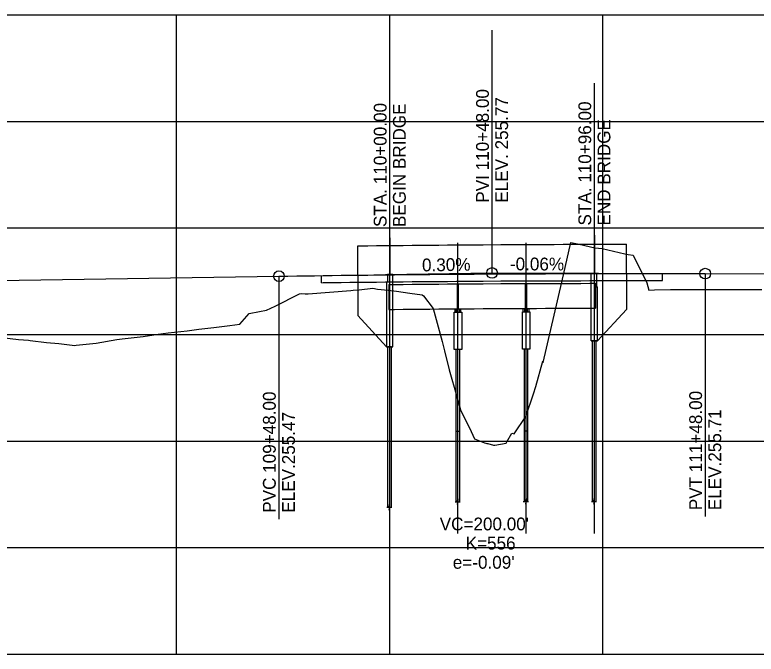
# Model space of a CAD drawing. Extents: x 1932071 to 1934815, y 598385 to 598883.
# Drawn here: x 1933216.8 to 1933564.6, y 598574.6 to 598874.6 of the extents above; entities that cross this region are included whole.
import ezdxf

# ---------------------------------------------------------------- set-up
doc = ezdxf.new("R2010")
doc.units = 0
for name, color, linetype in [('B_Centerline', 7, 'Continuous'), ('B_Concrete', 7, 'Continuous'), ('B_Pr_Abut_Wingwall', 7, 'Continuous'), ('B_Pr_Beam_Line', 7, 'Continuous'), ('B_Pr_Cap_Beams', 7, 'Continuous'), ('B_Pr_Columns', 7, 'Continuous'), ('B_Pr_Deck', 7, 'Continuous'), ('B_Pr_Rail', 7, 'Continuous'), ('BR_Pr_Cap_Beams', 7, 'Continuous'), ('Default', 7, 'Continuous'), ('R_Axis', 7, 'Continuous'), ('R_Exist Surface', 7, 'Continuous'), ('R_Grid', 7, 'Continuous'), ('R_Vert Alg', 7, 'Continuous'), ('R_Vert Alg Annot', 7, 'Continuous')]:
    doc.layers.add(name, color=color, linetype=linetype)

msp = doc.modelspace()

# ---------------------------------------------------------------- linework, layer by layer
at = {"layer": 'B_Centerline'}
for p, q in [((1933392.67, 598631.14), (1933392.67, 598767.58)), ((1933424.67, 598631.14), (1933424.67, 598767.58)), ((1933456.67, 598631.14), (1933456.67, 598767.58)), ((1933488.67, 598631.14), (1933488.67, 598767.58))]:
    msp.add_line(p, q, dxfattribs=at)
at = {"layer": 'B_Concrete'}
for p, q in [((1933377.67, 598752.42), (1933377.67, 598766.17)), ((1933503.67, 598753.17), (1933503.67, 598766.92)), ((1933360.67, 598748.87), (1933360.67, 598752.2)), ((1933520.67, 598749.83), (1933520.67, 598753.16))]:
    msp.add_line(p, q, dxfattribs=at)
for points in [[(1933377.67, 598766.17), (1933382.33, 598766.22), (1933386.5, 598766.27), (1933390.67, 598766.31), (1933394.83, 598766.35), (1933399, 598766.39), (1933403.17, 598766.43), (1933407.33, 598766.47), (1933411.5, 598766.51), (1933415.67, 598766.54), (1933419.83, 598766.58), (1933424, 598766.61), (1933428.17, 598766.64), (1933432.33, 598766.67), (1933436.5, 598766.7), (1933444.83, 598766.75), (1933449, 598766.77), (1933453.17, 598766.79), (1933457.33, 598766.81), (1933461.5, 598766.83), (1933465.67, 598766.84), (1933469.83, 598766.86), (1933474, 598766.87), (1933478.17, 598766.88), (1933482.33, 598766.89), (1933486.5, 598766.9), (1933490.67, 598766.91), (1933494.83, 598766.92), (1933499, 598766.92), (1933503.67, 598766.92)], [(1933360.67, 598748.87), (1933361.5, 598748.88), (1933365.67, 598748.94), (1933369.83, 598748.99), (1933374, 598749.04), (1933378.17, 598749.09), (1933382.33, 598749.14), (1933386.5, 598749.18), (1933390.67, 598749.23), (1933394.83, 598749.27), (1933399, 598749.31), (1933403.17, 598749.35), (1933407.33, 598749.39), (1933411.5, 598749.43), (1933415.67, 598749.46), (1933419.83, 598749.5), (1933424, 598749.53), (1933428.17, 598749.56), (1933432.33, 598749.59), (1933436.5, 598749.61), (1933444.83, 598749.66), (1933449, 598749.69), (1933453.17, 598749.71), (1933457.33, 598749.73), (1933461.5, 598749.75), (1933465.67, 598749.76), (1933469.83, 598749.78), (1933474, 598749.79), (1933478.17, 598749.8), (1933482.33, 598749.81), (1933486.5, 598749.82), (1933490.67, 598749.83), (1933494.83, 598749.83), (1933499, 598749.84), (1933503.17, 598749.84), (1933507.33, 598749.84), (1933511.5, 598749.84), (1933515.67, 598749.84), (1933519.83, 598749.83), (1933520.67, 598749.83)], [(1933392.17, 598747.99), (1933394.83, 598748.02), (1933399, 598748.06), (1933403.17, 598748.1), (1933407.33, 598748.14), (1933411.5, 598748.18), (1933415.67, 598748.21), (1933419.83, 598748.25), (1933424, 598748.28), (1933428.17, 598748.31), (1933432.33, 598748.34), (1933436.5, 598748.36), (1933444.83, 598748.41), (1933449, 598748.44), (1933453.17, 598748.46), (1933457.33, 598748.48), (1933461.5, 598748.5), (1933465.67, 598748.51), (1933469.83, 598748.53), (1933474, 598748.54), (1933478.17, 598748.55), (1933482.33, 598748.56), (1933486.5, 598748.57), (1933489.17, 598748.57)], [(1933392.17, 598736.33), (1933394.83, 598736.35), (1933399, 598736.4), (1933403.17, 598736.43), (1933407.33, 598736.47), (1933411.5, 598736.51), (1933415.67, 598736.55), (1933419.83, 598736.58), (1933424, 598736.61), (1933428.17, 598736.64), (1933432.33, 598736.67), (1933436.5, 598736.7), (1933444.83, 598736.75), (1933449, 598736.77), (1933453.17, 598736.79), (1933457.33, 598736.81), (1933461.5, 598736.83), (1933465.67, 598736.85), (1933469.83, 598736.86), (1933474, 598736.87), (1933478.17, 598736.88), (1933482.33, 598736.9), (1933486.5, 598736.9), (1933489.17, 598736.91)]]:
    msp.add_lwpolyline(points, dxfattribs=at)
at = {"layer": 'B_Pr_Abut_Wingwall'}
for p, q in [((1933489.67, 598753.16), (1933487.17, 598753.16)), ((1933487.17, 598721.56), (1933487.17, 598753.16)), ((1933489.67, 598753.16), (1933489.67, 598746.91)), ((1933489.67, 598746.91), (1933490.17, 598746.91)), ((1933490.17, 598721.56), (1933490.17, 598746.91))]:
    msp.add_line(p, q, dxfattribs=at)
msp.add_lwpolyline([(1933391.17, 598749.12), (1933391.17, 598718.78), (1933394.17, 598718.78), (1933394.17, 598752.7), (1933391.67, 598752.7), (1933391.67, 598749.12)], close=True, dxfattribs=at)
for points in [[(1933391.17, 598718.78), (1933394.17, 598718.78)], [(1933391.17, 598718.78), (1933394.17, 598718.78), (1933394.17, 598718.78)], [(1933391.17, 598718.78), (1933394.17, 598718.78), (1933394.17, 598718.78)], [(1933487.17, 598721.56), (1933490.17, 598721.56), (1933490.17, 598721.56)], [(1933487.17, 598721.56), (1933490.17, 598721.56), (1933490.17, 598721.56)], [(1933490.17, 598721.56), (1933487.17, 598721.56), (1933487.17, 598721.56)]]:
    msp.add_lwpolyline(points, dxfattribs=at)
at = {"layer": 'B_Pr_Beam_Line'}
for p, q in [((1933392.17, 598747.99), (1933392.17, 598736.33)), ((1933489.17, 598748.57), (1933489.17, 598736.91))]:
    msp.add_line(p, q, dxfattribs=at)
at = {"layer": 'B_Pr_Cap_Beams'}
for p, q in [((1933424.42, 598736.61), (1933424.42, 598748.28)), ((1933424.92, 598736.62), (1933424.92, 598748.28)), ((1933456.42, 598736.81), (1933456.42, 598748.47)), ((1933456.92, 598736.81), (1933456.92, 598748.48))]:
    msp.add_line(p, q, dxfattribs=at)
for points in [[(1933422.92, 598735.04), (1933426.42, 598735.04), (1933426.42, 598717.54), (1933422.92, 598717.54)], [(1933454.92, 598735.23), (1933458.42, 598735.23), (1933458.42, 598717.73), (1933454.92, 598717.73)]]:
    msp.add_lwpolyline(points, close=True, dxfattribs=at)
at = {"layer": 'B_Pr_Columns'}
for p, q in [((1933393.5, 598718.78), (1933391.83, 598718.78)), ((1933391.83, 598643.47), (1933391.83, 598718.78)), ((1933393.5, 598718.78), (1933391.83, 598718.78)), ((1933393.5, 598643.46), (1933393.5, 598718.78)), ((1933487.83, 598646.25), (1933487.83, 598721.56)), ((1933489.5, 598721.56), (1933487.83, 598721.56)), ((1933489.5, 598646.23), (1933489.5, 598721.56)), ((1933423.83, 598696.57), (1933423.83, 598717.54)), ((1933425.5, 598690.31), (1933425.5, 598717.54)), ((1933455.83, 598696.76), (1933455.83, 598717.73)), ((1933457.5, 598690.5), (1933457.5, 598717.73)), ((1933423.83, 598646.05), (1933423.83, 598696.57)), ((1933455.83, 598646.24), (1933455.83, 598696.76)), ((1933425.5, 598646.05), (1933425.5, 598690.31)), ((1933457.5, 598646.24), (1933457.5, 598690.5)), ((1933425.5, 598679), (1933423.83, 598679)), ((1933457.5, 598679.19), (1933455.83, 598679.19))]:
    msp.add_line(p, q, dxfattribs=at)
at = {"layer": 'B_Pr_Deck'}
for p, q in [((1933377.67, 598752.42), (1933392.67, 598752.7)), ((1933488.67, 598749.62), (1933488.67, 598753.16))]:
    msp.add_line(p, q, dxfattribs=at)
for points in [[(1933377.67, 598752.42), (1933377.67, 598733.43), (1933391.17, 598718.78)], [(1933503.67, 598753.17), (1933503.67, 598736.21), (1933490.17, 598721.56)]]:
    msp.add_lwpolyline(points, dxfattribs=at)
at = {"layer": 'B_Pr_Rail'}
for p, q in [((1933488.67, 598771.09), (1933488.67, 598753.59)), ((1933392.67, 598769.99), (1933392.67, 598753.14)), ((1933392.67, 598752.58), (1933392.67, 598769.99))]:
    msp.add_line(p, q, dxfattribs=at)
at = {"layer": 'BR_Pr_Cap_Beams'}
for p, q in [((1933423.33, 598735.04), (1933423.33, 598736.66)), ((1933424, 598735.04), (1933424, 598736.64)), ((1933425.33, 598735.04), (1933425.33, 598736.59)), ((1933426, 598735.04), (1933426, 598736.57)), ((1933455.33, 598735.23), (1933455.33, 598736.85)), ((1933456, 598735.23), (1933456, 598736.83)), ((1933457.33, 598735.23), (1933457.33, 598736.78)), ((1933458, 598735.23), (1933458, 598736.76))]:
    msp.add_line(p, q, dxfattribs=at)
at = {"layer": 'Default'}
for p, q in [((1933424.66, 598646.04), (1933425.68, 598646.04)), ((1933456.66, 598646.23), (1933457.68, 598646.23)), ((1933488.65, 598646.23), (1933489.67, 598646.23)), ((1933392.65, 598643.46), (1933393.67, 598643.46))]:
    msp.add_line(p, q, dxfattribs=at)
for points in [[(1933423.33, 598646.05), (1933424.4, 598646.05), (1933424.59, 598647.44), (1933424.46, 598644.77), (1933424.66, 598646.04)], [(1933455.33, 598646.25), (1933456.4, 598646.25), (1933456.59, 598647.63), (1933456.46, 598644.96), (1933456.66, 598646.23)], [(1933487.32, 598646.25), (1933488.39, 598646.25), (1933488.58, 598647.63), (1933488.45, 598644.96), (1933488.65, 598646.23)], [(1933391.32, 598643.47), (1933392.39, 598643.47), (1933392.58, 598644.85), (1933392.45, 598642.18), (1933392.65, 598643.46)]]:
    msp.add_lwpolyline(points, dxfattribs=at)
at = {"layer": 'R_Axis'}
for p, q in [((1933292.67, 598824.55), (1933292.67, 598826.05)), ((1933292.67, 598824.55), (1933292.67, 598825.8)), ((1932092.67, 598574.55), (1934792.67, 598574.55))]:
    msp.add_line(p, q, dxfattribs=at)
at = {"layer": 'R_Exist Surface'}
msp.add_lwpolyline([(1933209.27, 598723.34), (1933218.42, 598722.26), (1933223.26, 598721.84), (1933224.03, 598721.75), (1933231.67, 598720.82), (1933237.36, 598720.32), (1933244.9, 598719.41), (1933245.57, 598719.49), (1933254.98, 598720.56), (1933264.62, 598722.28), (1933267.1, 598722.56), (1933277.01, 598723.65), (1933283.98, 598724.78), (1933288.63, 598725.29), (1933297.63, 598726.28), (1933303.17, 598727.13), (1933310.06, 598727.89), (1933317.66, 598728.76), (1933322.27, 598729.46), (1933326.77, 598734.48), (1933331.49, 598735.32), (1933334.89, 598735.93), (1933338.88, 598737.85), (1933350.28, 598743.66), (1933351.14, 598743.74), (1933352.91, 598743.67), (1933354.36, 598743.62), (1933374.34, 598745.22), (1933375.56, 598745.32), (1933378.34, 598745.5), (1933384.67, 598746.23), (1933386.88, 598745.75), (1933391.97, 598745.36), (1933395.77, 598744.82), (1933402.09, 598743.93), (1933407.81, 598743.15), (1933408.51, 598742.63), (1933412.96, 598736.79), (1933417.19, 598721.23), (1933418.39, 598716.82), (1933420.5, 598708.03), (1933424.14, 598695.53), (1933425.79, 598689.21), (1933430.81, 598679.02), (1933432.42, 598675.56), (1933437.09, 598673.75), (1933437.74, 598673.58), (1933438.26, 598673.45), (1933438.62, 598673.36), (1933441.31, 598672.68), (1933442, 598672.58), (1933447.35, 598673.56), (1933447.63, 598674.23), (1933450, 598678.21), (1933450.99, 598677.98), (1933456.48, 598686.05), (1933460.05, 598696.67), (1933461.23, 598700.2), (1933464.55, 598712.1), (1933464.65, 598711.48), (1933473.44, 598749.08), (1933477.55, 598767.74), (1933481.47, 598766.88), (1933488.92, 598765.25), (1933492.38, 598764.85), (1933502.9, 598762.46), (1933504.48, 598762.1), (1933506.8, 598761.83), (1933513.21, 598748.74), (1933514.19, 598745.3), (1933516.88, 598745.55), (1933524.33, 598745.61), (1933535.15, 598745.7), (1933537.68, 598745.72), (1933545.75, 598745.69), (1933558.49, 598745.63), (1933559.98, 598745.64), (1933561.32, 598745.65), (1933567.18, 598745.62)], dxfattribs=at)
at = {"layer": 'R_Grid'}
for p, q in [((1932092.67, 598874.55), (1934792.67, 598874.55)), ((1932092.67, 598874.55), (1934792.67, 598874.55)), ((1933292.67, 598574.55), (1933292.67, 598874.55)), ((1933392.67, 598574.55), (1933392.67, 598874.55)), ((1933492.67, 598574.55), (1933492.67, 598874.55)), ((1932092.67, 598824.55), (1934792.67, 598824.55)), ((1932092.67, 598774.55), (1934792.67, 598774.55)), ((1932092.67, 598724.55), (1934792.67, 598724.55)), ((1932092.67, 598674.55), (1934792.67, 598674.55)), ((1932092.67, 598624.55), (1934792.67, 598624.55))]:
    msp.add_line(p, q, dxfattribs=at)
at = {"layer": 'R_Vert Alg'}
for p, q in [((1933390.67, 598752.67), (1933440.67, 598753.42)), ((1933390.67, 598752.67), (1933440.67, 598753.42)), ((1933390.67, 598752.67), (1933440.67, 598753.42)), ((1933440.67, 598753.42), (1933490.67, 598753.27)), ((1933440.67, 598753.42), (1933490.67, 598753.27)), ((1933440.67, 598753.42), (1933490.67, 598753.27)), ((1933156.67, 598749.16), (1933340.67, 598751.92)), ((1933540.67, 598753.12), (1934265.61, 598750.95))]:
    msp.add_line(p, q, dxfattribs=at)
msp.add_lwpolyline([(1933340.67, 598751.92), (1933344.83, 598751.98), (1933349, 598752.04), (1933353.17, 598752.1), (1933357.33, 598752.16), (1933361.5, 598752.22), (1933365.67, 598752.27), (1933369.83, 598752.32), (1933374, 598752.37), (1933378.17, 598752.42), (1933382.33, 598752.47), (1933386.5, 598752.52), (1933390.67, 598752.56), (1933394.83, 598752.6), (1933399, 598752.64), (1933403.17, 598752.68), (1933407.33, 598752.72), (1933411.5, 598752.76), (1933415.67, 598752.79), (1933419.83, 598752.83), (1933424, 598752.86), (1933428.17, 598752.89), (1933432.33, 598752.92), (1933436.5, 598752.95), (1933444.83, 598753), (1933449, 598753.02), (1933453.17, 598753.04), (1933457.33, 598753.06), (1933461.5, 598753.08), (1933465.67, 598753.09), (1933469.83, 598753.11), (1933474, 598753.12), (1933478.17, 598753.13), (1933482.33, 598753.14), (1933486.5, 598753.15), (1933490.67, 598753.16), (1933494.83, 598753.17), (1933499, 598753.17), (1933503.17, 598753.17), (1933507.33, 598753.17), (1933511.5, 598753.17), (1933515.67, 598753.17), (1933519.83, 598753.17), (1933524, 598753.16), (1933528.17, 598753.15), (1933532.33, 598753.14), (1933536.5, 598753.13), (1933540.67, 598753.12)], dxfattribs=at)
msp.add_lwpolyline([(1933340.67, 598751.92), (1933344.83, 598751.98), (1933349, 598752.04), (1933353.17, 598752.1), (1933357.33, 598752.16), (1933361.5, 598752.22), (1933365.67, 598752.27), (1933369.83, 598752.32), (1933374, 598752.37), (1933378.17, 598752.42), (1933382.33, 598752.47), (1933386.5, 598752.52), (1933390.67, 598752.56), (1933394.83, 598752.6), (1933399, 598752.64), (1933403.17, 598752.68), (1933407.33, 598752.72), (1933411.5, 598752.76), (1933415.67, 598752.79), (1933419.83, 598752.83), (1933424, 598752.86), (1933428.17, 598752.89), (1933432.33, 598752.92), (1933436.5, 598752.95), (1933444.83, 598753), (1933449, 598753.02), (1933453.17, 598753.04), (1933457.33, 598753.06), (1933461.5, 598753.08), (1933465.67, 598753.09), (1933469.83, 598753.11), (1933474, 598753.12), (1933478.17, 598753.13), (1933482.33, 598753.14), (1933486.5, 598753.15), (1933490.67, 598753.16), (1933494.83, 598753.17), (1933499, 598753.17), (1933503.17, 598753.17), (1933507.33, 598753.17), (1933511.5, 598753.17), (1933515.67, 598753.17), (1933519.83, 598753.17), (1933524, 598753.16), (1933528.17, 598753.15), (1933532.33, 598753.14), (1933536.5, 598753.13), (1933540.67, 598753.12)], dxfattribs=at)
at = {"layer": 'R_Vert Alg Annot'}
for p, q in [((1933440.67, 598783.42), (1933440.67, 598867.42)), ((1933392.67, 598782.58), (1933392.67, 598841.81)), ((1933488.67, 598783.28), (1933488.67, 598842.51)), ((1933392.67, 598752.58), (1933392.67, 598782.58)), ((1933440.67, 598753.42), (1933440.67, 598783.42)), ((1933488.67, 598753.28), (1933488.67, 598783.28)), ((1933340.67, 598751.92), (1933340.67, 598721.92)), ((1933540.67, 598753.12), (1933540.67, 598723.12)), ((1933540.67, 598723.12), (1933540.67, 598639.12)), ((1933340.67, 598721.92), (1933340.67, 598637.92))]:
    msp.add_line(p, q, dxfattribs=at)
for centre in [(1933340.67, 598751.92), (1933440.67, 598753.42), (1933540.67, 598753.12)]:
    msp.add_circle(centre, 2.5, dxfattribs=at)

# ---------------------------------------------------------------- texts
for s, rotation, p in [('PVI 110+48.00', 90, (1933439.17, 598786.42)), ('ELEV. 255.77', 90, (1933448.17, 598786.42)), ('STA. 110+96.00', 90, (1933487.17, 598775.69)), ('STA. 110+00.00', 90, (1933391.17, 598774.99)), ('BEGIN BRIDGE', 90, (1933400.17, 598774.99)), ('END BRIDGE', 90, (1933496.17, 598775.69)), ('0.30%', 0.8594, (1933407.84, 598754.15)), ('-0.06%', 359.8281, (1933449.03, 598754.67)), ('PVT 111+48.00', 90, (1933539.17, 598642.12)), ('PVC 109+48.00', 90, (1933339.17, 598640.92)), ('ELEV.255.47', 90, (1933348.17, 598640.92)), ('ELEV.255.71', 90, (1933548.17, 598642.12))]:
    msp.add_text(s, height=6, rotation=rotation, dxfattribs=at).set_placement(p)
for s, p in [("VC=200.00'", (1933416.1, 598632.65)), ('K=556', (1933428.27, 598623.65)), ("e=-0.09'", (1933422.24, 598614.65))]:
    msp.add_text(s, height=6, dxfattribs=at).set_placement(p)

doc.saveas('drawing.dxf')
